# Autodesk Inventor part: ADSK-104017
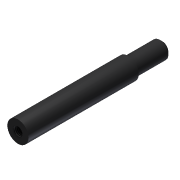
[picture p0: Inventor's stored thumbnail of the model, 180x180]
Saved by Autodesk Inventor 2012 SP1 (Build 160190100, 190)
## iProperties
Shininess: 27.0
Created: 2001-05
Part Number: ADSK-104017
Document SubType Name: Modeling
Designer: Administrator
Stock Number: ADSK-104017
Density: 1 g/cm^3
Material: Default
Density: 0.0
Volumn: 0.0
Area: 0.0
PropertySet Name: Model Information
Control State: 0
Master: False
Checked Out: False
Author: Administrator
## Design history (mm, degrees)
sketch "Sketch1"
  geometry: C1 r 15.875 at (0, 0)
  constraints: 1 centre point
  dimensions: "d0" = 31.75 diameter of C1
extrude "Extrusion1" new body sketch "Sketch1" distance "d1" = 215.9; taper "d2" = 0 deg
sketch "Sketch2"
  geometry: L1 (0, 0)-(-10.135, -12.219); 1 further point
  constraints: 2 end point, 1 coincident, 2 other
hole "Hole1" sketch "Sketch2" at (0, 0) diameter "d4" = 13.3858; stored, may be unused: countersink angle "d8" = 60 deg, drill point angle "d10" = 118 deg; dims "d5" = 25.4, "d6" = 9.525, "d7" = 6.35, "d9" = 31.75
sketch "Sketch5"
  geometry: C1 r 15.875 at (0, 0) reference; C2 r 12.7 at (0, 0)
  constraints: 1 centre point
  dimensions: "d21" = 25.4 diameter of C2
extrude "Extrusion3" cut sketch "Sketch5" distance "d22" = 50.8; taper "d23" = 0 deg
chamfer "Chamfer1" distance "d24" = 3.175; stored, may be unused: second distance "d25" = 3.175, angle "d26" = 45 deg
body "Solid1"
other parameters: "d3" = 25.4 (derived)
